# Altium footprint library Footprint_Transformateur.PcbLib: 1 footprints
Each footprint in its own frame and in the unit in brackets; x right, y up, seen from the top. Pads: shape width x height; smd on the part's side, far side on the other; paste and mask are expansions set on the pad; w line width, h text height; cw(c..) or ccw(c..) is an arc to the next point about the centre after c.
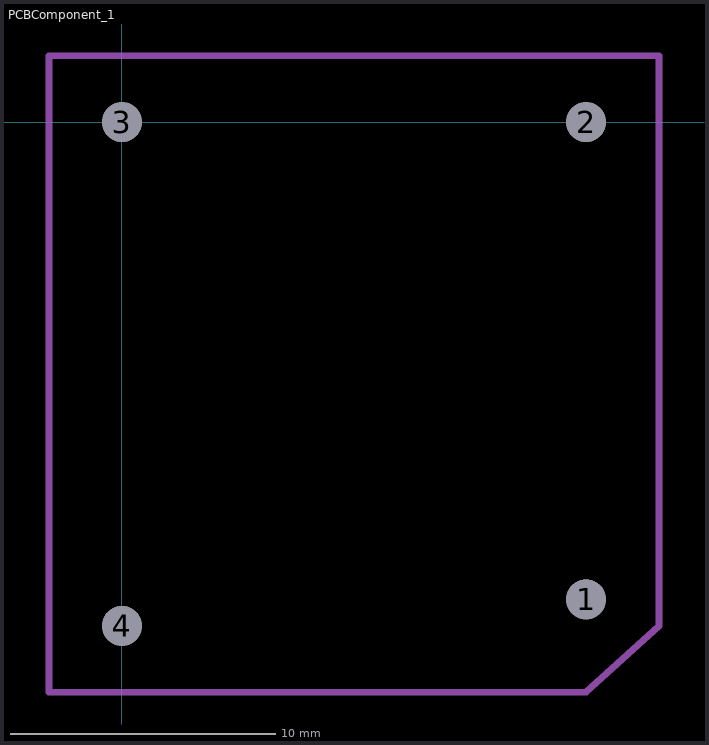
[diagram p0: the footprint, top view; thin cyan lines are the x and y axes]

## PCBComponent_1 [mm]
pads (4):
  round 1.5 hole 1.5: 1(17.5,-18) 2(17.5,0) 3(0,0) 4(0,-19)
Mechanical 1:
  lines w0.254: -2.75,-21.5 -2.75,2.5 20.25,2.5 20.25,-19 17.5,-21.5 -2.75,-21.5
